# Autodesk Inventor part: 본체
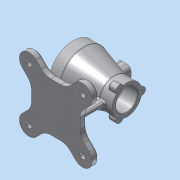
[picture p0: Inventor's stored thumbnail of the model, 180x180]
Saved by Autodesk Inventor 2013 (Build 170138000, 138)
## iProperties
Created: 2018-03
Part Number: 본체
Material: 알루미늄 6061
Document SubType Name: Modeling
Designer: Administrator
Density: 2.71 g/cm^3
Mass: 1014.37 g
Surface Area: 854.98 cm^2
Volume: 374.307 cm^3
Author: Administrator
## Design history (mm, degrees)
sketch "스케치1"
  geometry: L1 (-50, 0)-(-50, 45); L2 (50, 27.5)-(50, 0); L3 (50, 0)-(-50, 0); L4 (-70, 0)-(70, 0) reference; L5 (-50, 45)-(-30, 45); L6 (0, 54)-(0, -9) reference; L7 (-30, 45)-(27, 27.5); L8 (50, 27.5)-(27, 27.5); 1 further point
  constraints: 12 end point, 2 parallel, 2 perpendicular, 1 vertical, 1 other
  dimensions: "d0" = 90 diameter of L1.end L4; "d1" = 55 diameter of L2.start L4; "d2" = 20 distance of L1.end L5.end; "d3" = 100 distance of L2.end L1.start; "d4" = 45 distance of L1.end L1.start; "d58" = 77 distance from line of L7.end L1
revolve "회전1" sketch "스케치1" stored, may be unused: angle "d5" = 90 deg
node "작업 평면1"
sketch "스케치2"
  geometry: L1 (-0.013, 0.013)-(49.485, 49.51); L2 (-104.917, 0)-(104.917, 0) reference; L3 (0, -104.952)-(0, 104.952) reference; L4 (0, 25.481)-(36.757, 62.238); L5 (25.43, 0)-(62.213, 36.782); L6 (0, 25.481)-(-36.757, 62.238); L7 (-25.43, 0)-(-62.213, 36.782); L8 (0, -25.481)-(36.757, -62.238); L9 (0, -25.481)-(-36.757, -62.238); L10 (25.43, 0)-(62.213, -36.782); L11 (-25.43, 0)-(-62.213, -36.782); L12 (-45.013, 45.013)-(44.987, 45.013); L13 (44.987, 45.013)-(44.987, -44.987); L14 (44.987, -44.987)-(-45.013, -44.987); L15 (-45.013, -44.987)-(-45.013, 45.013); L16 (-45.013, 45.013)-(44.987, -44.987); L17 (44.987, 45.013)-(-45.013, -44.987); A1 r 70 centre (-0.013, 0.013) between (49.485, 49.51) and (35.226, 60.496); A2 r 18 centre (49.485, 49.51) between (60.471, 35.251) and (35.226, 60.496); A3 r 18 centre (-49.485, 49.51) between (-35.226, 60.496) and (-60.471, 35.251); A4 r 18 centre (49.485, -49.51) between (35.226, -60.496) and (60.471, -35.251); A5 r 18 centre (-49.485, -49.51) between (-60.471, -35.251) and (-35.226, -60.496)
  constraints: 30 end point, 19 point on circle, 17 symmetric about line, 5 centre point, 4 parallel, 2 midpoint, 2 point on line, 1 horizontal, 1 perpendicular, 4 other
  dimensions: "d11" = 140 diameter of A1; "d12" = 45 deg angle of L1 L2; "d14" = 36 diameter of A2; "d15" = 36 distance between parallel lines of L4 L5; "d16" = 25.46855 distance of L1.start L4.start; "d17" = 25.43042 distance from line of L3 L5.start; "d18" = 90 distance of L13.end L14.end; "d19" = 90 distance of L12.end L13.end
extrude "돌출1" join sketch "스케치2" distance "d20" = 12; taper "d21" = 0 deg
sketch "스케치3"
  geometry: L1 (-37, 4)-(37, 4); L2 (37, 4)-(37, -4); L3 (37, -4)-(-37, -4); L4 (-37, -4)-(-37, 4); L5 (-37, 4)-(37, -4); L6 (37, 4)-(-37, -4); 1 further point
  constraints: 12 end point, 2 midpoint, 2 parallel, 1 horizontal, 1 perpendicular
  dimensions: "d22" = 74 distance of L2.end L3.end; "d24" = 8 distance of L1.end L2.end
extrude "돌출2" join sketch "스케치3" stored distance "d25" = 12; taper "d26" = 0 deg
sketch "스케치4"
  geometry: 1 further point
sketch "스케치5"
  geometry: 1 further point
sketch "스케치6"
  geometry: L1 (-70, -24)-(-35.267, -20.961); L2 (-70, -19.582)-(-70, -36.782) reference; 1 further point
  constraints: 2 end point, 1 point on line
  dimensions: "d29" = 24 vertical distance of point (0, 0) L1.start; "d30" = 95 deg angle of L2 L1
feature "리브1" sketch "스케치6" dims "d31" = 1, "d32" = 8, "d33" = 0, "d34" = 0, "d35" = 1, "d36" = 1
node "작업 평면3"
sketch "스케치7"
  geometry: L1 (-52.5, 12.5)-(-27.5, 12.5); L2 (-27.5, 12.5)-(-27.5, -12.5); L3 (-27.5, -12.5)-(-52.5, -12.5); L4 (-52.5, -12.5)-(-52.5, 12.5); L5 (-52.5, 12.5)-(-27.5, -12.5); L6 (-27.5, 12.5)-(-52.5, -12.5); L7 (10, 45)-(10, -45) reference; L8 (-134.479, 0)-(54.479, 0) reference; L9 (-47.5, 7.5)-(-32.5, -7.5); L10 (-32.5, 7.5)-(-47.5, -7.5); 3 further points
  constraints: 16 end point, 6 midpoint, 2 parallel, 1 horizontal, 1 perpendicular, 1 point on line
  dimensions: "d37" = 50 distance from line of L7 point (-40, 0); "d38" = 25 distance of L2.end L3.end; "d39" = 25 distance of L1.end L2.end
extrude "돌출3" join sketch "스케치7" stored distance "d41" = 12; taper "d42" = 0 deg
sketch "스케치8"
  geometry: L1 (47.5, 7.5)-(32.5, 7.5); L2 (32.5, 7.5)-(32.5, -7.5); L3 (32.5, -7.5)-(47.5, -7.5); L4 (47.5, -7.5)-(47.5, 7.5); L5 (47.5, 7.5)-(32.5, -7.5); L6 (32.5, 7.5)-(47.5, -7.5); 1 further point
  constraints: 12 end point, 2 midpoint, 2 parallel, 1 horizontal, 1 perpendicular
  dimensions: "d43" = 15 distance of L3.end L2.end; "d44" = 15 distance of L3.end L1.start
extrude "돌출4" cut sketch "스케치8" distance "d45" = 30; taper "d46" = 0 deg
sketch "스케치9"
  geometry: L1 (-50, 0)-(-50, 35); L2 (-50, 35)-(-27, 35); L3 (-27, 35)-(-27, 26); L4 (-27, 26)-(20, 26); L5 (20, 26)-(20, 20); L6 (20, 20)-(50, 20); L7 (50, 20)-(50, 0); L8 (50, 0)-(-50, 0); L9 (-50, -45)-(-50, 45) reference; L10 (50, -27.5)-(50, 27.5) reference; L11 (-7.5, 45)-(7.5, 45) reference; 3 further points
  constraints: 16 end point, 5 parallel, 2 midpoint, 2 perpendicular, 2 point on line, 1 vertical
  dimensions: "d47" = 23 distance of L1.end L2.end; "d49" = 47 distance of L3.end L4.end; "d50" = 70 diameter of L2 L8; "d51" = 52 diameter of L4 L8; "d52" = 40 diameter of L6 L8; "d53" = 45 distance between parallel lines of L11 L8
revolve "회전2" sketch "스케치9" stored, may be unused: angle "d54" = 90 deg
sketch "스케치10"
  geometry: 1 further point
sketch "스케치11"
  geometry: C1 r 7 at (0, 27.5); 1 further point
  constraints: 1 centre point, 1 vertical alignment, 1 other
  dimensions: "d55" = 14 diameter of C1
extrude "돌출5" join sketch "스케치11" distance "d56" = 15; taper "d57" = 0 deg
hole "구멍1" diameter "d64" = 10; stored, may be unused: countersink angle "d68" = 90 deg, drill point angle "d70" = 118 deg; dims "d62" = 10, "d63" = 10, "d65" = 6, "d66" = 4, "d67" = 2, "d69" = 8
hole "구멍2" diameter "d73" = 10; stored, may be unused: countersink angle "d77" = 90 deg, drill point angle "d79" = 118 deg; dims "d71" = 10, "d72" = 10, "d74" = 6, "d75" = 4, "d76" = 2, "d78" = 8
sketch "스케치12" dims "d80" = 80
  geometry: C1 r 45 at (0, 0) reference; 2 further points
  constraints: 1 coincident, 1 vertical alignment, 2 other
hole "구멍3" sketch "스케치12" at (0, 40) diameter "d81" = 3.242; stored, may be unused: countersink angle "d85" = 90 deg, drill point angle "d87" = 118 deg; dims "d82" = 9, "d83" = 4, "d84" = 2, "d86" = 11
hole "구멍4" diameter "d93" = 3.242; stored, may be unused: countersink angle "d97" = 90 deg, drill point angle "d99" = 118 deg; dims "d91" = 10, "d92" = 10, "d94" = 9, "d95" = 4, "d96" = 2, "d98" = 11
fillet "모깎기1" dims "d103" = 25
fillet "모깎기2" dims "d104" = 8
fillet "모깎기3" dims "d105" = 3
fillet "모깎기4" dims "d106" = 3
fillet "모깎기5" dims "d107" = 1
fillet "모깎기6" dims "d108" = 1
chamfer "모따기1" distance "d109" = 3; stored, may be unused: second distance "d110" = 2, angle "d111" = 45 deg
chamfer "모따기2" distance "d112" = 1; stored, may be unused: second distance "d113" = 2, angle "d114" = 45 deg
fillet "모깎기7" dims "d115" = 3
fillet "모깎기8" dims "d116" = 3
fillet "모깎기9" dims "d117" = 3
fillet "모깎기10" dims "d118" = 3
node "작업 평면4"
sketch "스케치13"
  geometry: L1 (45.013, -9.227)-(45.013, 9.227) reference; 2 further points
  constraints: 1 other
  dimensions: "d120" = 35 distance of point (0, 0) point (0.013, -35); "d121" = 45 distance from line of L1 point (0.013, -35)
feature "엠보싱1" sketch "스케치13" dims "d11" = 140, "d12" = 45 deg, "d14" = 36, "d15" = 36, "d16" = 25.46855, "d17" = 25.43042, "d18" = 90, "d19" = 90, "d122" = 0.5, "d123" = 0
node "솔리드1"
mirror "대칭1"
pattern_circular "원형 패턴1" dims angle "d60" = 360 deg
mirror "대칭2"
pattern_circular "원형 패턴2" dims angle "d89" = 360 deg
pattern_circular "원형 패턴3" dims angle "d101" = 360 deg
other parameters: "d6" = -82, "d119" = 0.5
